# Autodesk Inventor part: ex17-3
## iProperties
Created: 2006-04
Part Number: ex17-3
Document SubType Name: Modeling
Designer: E. MOSS
Project: EVERGREEN VALLEY COLLEGE
Description: PLATE
Authority: MS. TEACHER
Author: E. MOSS
Revision Number: A
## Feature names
1. Extrusion1
2. Hole1
3. Extrusion2
